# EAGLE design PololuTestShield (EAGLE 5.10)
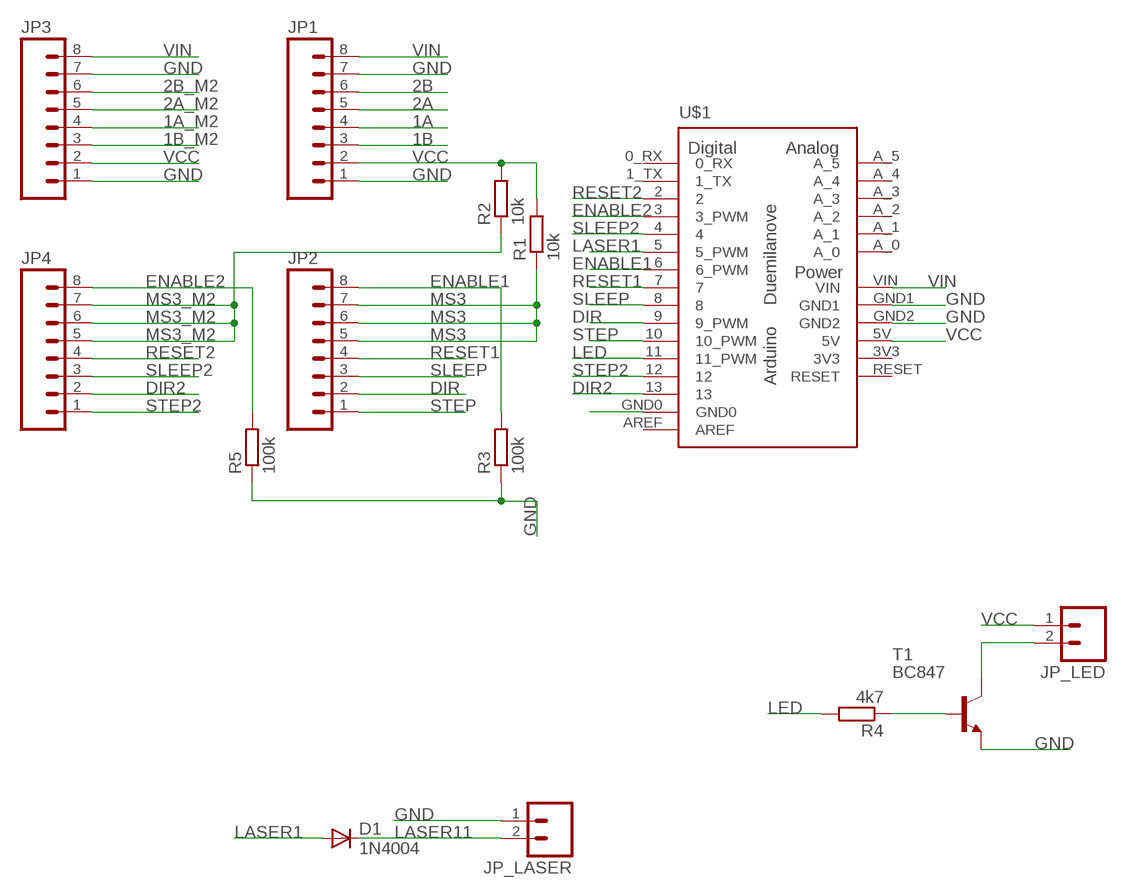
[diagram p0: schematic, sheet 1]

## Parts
D1  1N4004  [DO41-10]
JP1  M08LOCK_LONGPADS  [1X08_LOCK_LONGPADS]
JP2  M08LOCK_LONGPADS  [1X08_LOCK_LONGPADS]
JP3  M08LOCK_LONGPADS  [1X08_LOCK_LONGPADS]
JP4  M08LOCK_LONGPADS  [1X08_LOCK_LONGPADS]
JP_LASER  M02LOCK_LONGPADS  [1X02_LOCK_LONGPADS]
JP_LED  M02LOCK_LONGPADS  [1X02_LOCK_LONGPADS]
R1  10k  R-EU_M1206  [M1206]
R2  10k  R-EU_M1206  [M1206]
R3  100k  R-EU_M1206  [M1206]
R4  4k7  R-EU_M1206  [M1206]
R5  100k  R-EU_M1206  [M1206]
T1  BC847  [SOT23]
U$1  ARDUINO-USBLONG_PADS_TEXT  [SHIELD]

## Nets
1A: JP1.4
1A_M2: JP3.4
1B: JP1.3
1B_M2: JP3.3
2A: JP1.5
2A_M2: JP3.5
2B: JP1.6
2B_M2: JP3.6
DIR: JP2.2 U$1.9(9_PWM)
DIR2: JP4.2 U$1.13
ENABLE1: JP2.8 R3.2 U$1.6(6_PWM)
ENABLE2: JP4.8 R5.2 U$1.3(3_PWM)
GND: JP1.1 JP1.7 JP3.1 JP3.7 JP_LASER.1 R3.1 R5.1 T1.2(E) U$1.GND0 U$1.GND1 U$1.GND2
LASER1: D1.A U$1.5(5_PWM)
LASER11: D1.C JP_LASER.2
LED: R4.2 U$1.11(11_PWM)
MS3: JP2.5 JP2.6 JP2.7 R1.1
MS3_M2: JP4.5 JP4.6 JP4.7 R2.1
N$1: R4.1 T1.1(B)
N$2: JP_LED.2 T1.3(C)
RESET1: JP2.4 U$1.7
RESET2: JP4.4 U$1.2
SLEEP: JP2.3 U$1.8
SLEEP2: JP4.3 U$1.4
STEP: JP2.1 U$1.10(10_PWM)
STEP2: JP4.1 U$1.12
VCC: JP1.2 JP3.2 JP_LED.1 R1.2 R2.2 U$1.5V
VIN: JP1.8 JP3.8 U$1.VIN
Unconnected: U$1.0_RX U$1.1_TX U$1.A_0 U$1.A_1 U$1.A_2 U$1.A_3 U$1.A_4 U$1.A_5 U$1.AREF U$1.RESET

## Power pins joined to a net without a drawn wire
3V3: U$1.3V3

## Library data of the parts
D1 = diode:1N4004: DIODE
JP1-JP4 = SparkFun:M08: Header 8 Standard 8-pin 0.1" header. Use with straight break away headers (SKU : PRT-00116), right angle break away headers (PRT-00553), swiss pins (PRT-00743), machine pins (PRT-00117), and female headers (PRT-00115).
JP_LASER JP_LED = SparkFun:M02: Header 2
R1-R5 = rcl:R-EU_: RESISTOR, European symbol
T1 = transistor-neu-to92:BC847: NPN TRANSISTOR
U$1 = Arduino-Various:ARDUINO-USB: The Ardiuno Duemilanove Pinouts layoutet as a Bare Shield. v0.5 Also for Arduino Diecimila. This is designed as a Part and has no Outline in the Dimension Layer. The Outline, when present, is drawed at the tPlace / bPlace Layer. Library by Stephanie Lange, http://www.k-ita.de/~sl/

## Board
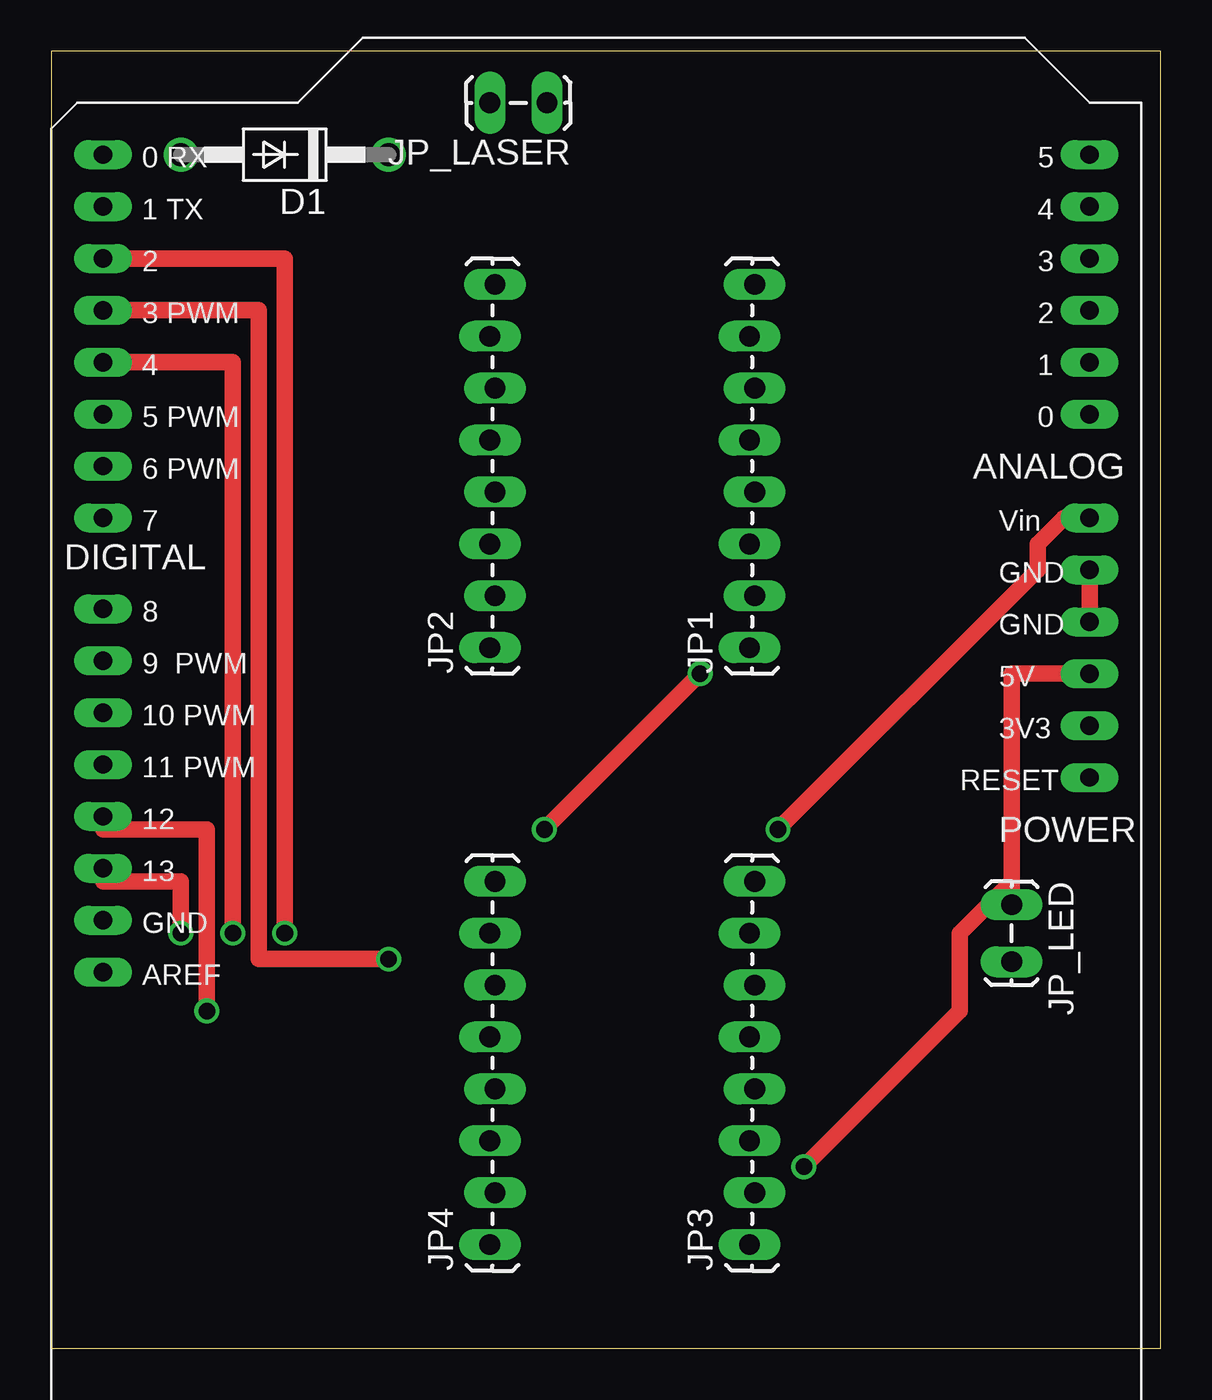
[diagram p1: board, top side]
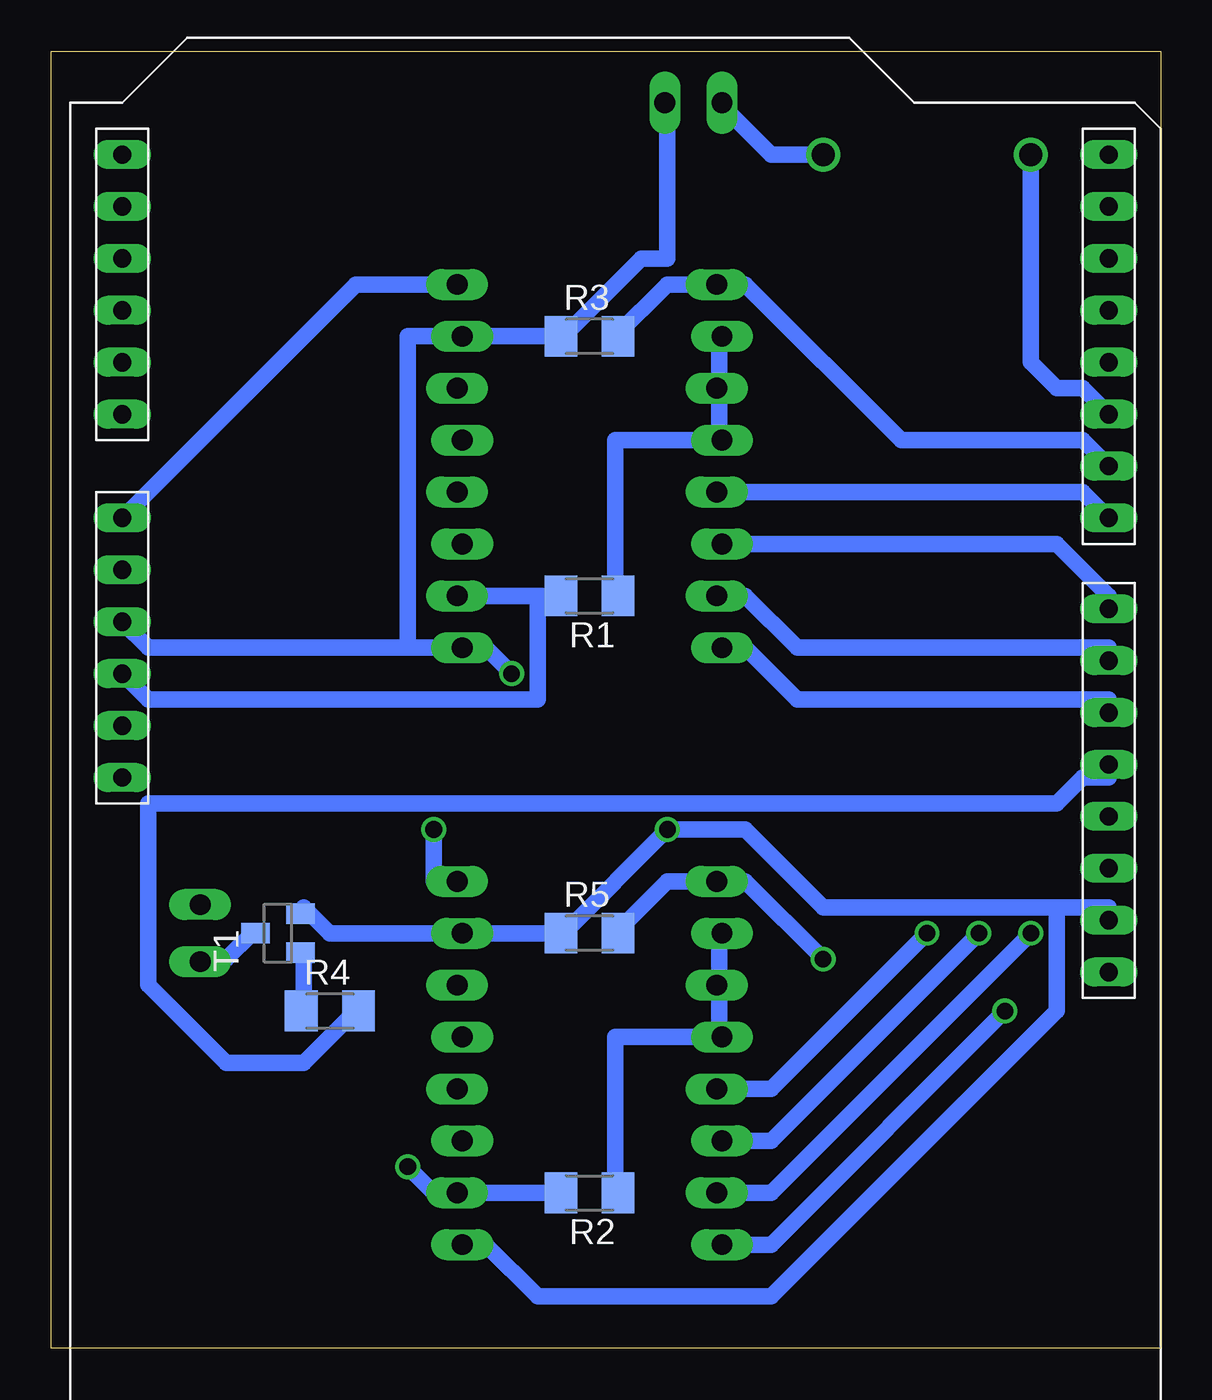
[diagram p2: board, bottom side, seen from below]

Size 54.28 x 63.49 mm. Coordinates in mm from the lower left corner, seen from the top.
Outline: 0,0 54.28,0 54.28,63.49 0,63.49 0,0
Copper layers (1*16): Top 0.035mm / dielectric 1.5mm / Bottom 0.035mm
Design rules "default *": minimum track width 32mil, minimum drill 32mil, track to track 8mil, track to pad 8mil, pad to pad 8mil, via to via 8mil, smd to smd 8mil, copper to edge 40mil, drill to drill 8mil, minimum pad ring 10mil, minimum via ring 8mil, stop-mask expansion 4mil, vias tented up to drill 0mil, thermal gap 10mil
tRestrict: area 20.3,33 to 22.9,53.3; area 33,33 to 35.6,53.3; area 20.3,3.8 to 22.9,24.1; area 33,3.8 to 35.6,24.1; area 20.3,59.7 to 25.4,62.2

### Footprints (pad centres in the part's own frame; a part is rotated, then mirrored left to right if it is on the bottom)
DO41-10 = drill 1.118 round: A 5.08,0; C -5.08,0
1X08_LOCK_LONGPADS = drill 1.016 long: 1 0,0.127; 2 2.54,-0.127; 3 5.08,0.127; 4 7.62,-0.127; 5 10.16,0.127; 6 12.7,-0.127; 7 15.24,0.127; 8 17.78,-0.127
1X02_LOCK_LONGPADS = drill 1.016 long: 1 -0.127,0; 2 2.667,0
M1206 = smd 1.6 x 2: 1 -1.4,0; 2 1.4,0
SOT23 = smd 1 x 1.4: 1 -0.95,-1.1; 2 0.95,-1.1; 3 0,1.1
SHIELD = drill 0.9 pad 1.27 long: 0_RX -25.4,27.94; 1_TX -25.4,25.4; 2 -25.4,22.86; 3 -25.4,20.32; 3V3 22.86,0; 4 -25.4,17.78; 5 -25.4,15.24; 5V 22.86,2.54; 6 -25.4,12.7; 7 -25.4,10.16; 8 -25.4,5.715; 9 -25.4,3.175; 10 -25.4,0.635; 11 -25.4,-1.905; 12 -25.4,-4.445; 13 -25.4,-6.985; A_0 22.86,15.24; A_1 22.86,17.78; A_2 22.86,20.32; A_3 22.86,22.86; A_4 22.86,25.4; A_5 22.86,27.94; AREF -25.4,-12.065; GND0 -25.4,-9.525; GND1 22.86,7.62; GND2 22.86,5.08; RESET 22.86,-2.54; VIN 22.86,10.16

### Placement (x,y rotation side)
D1  11.43,58.42 180 top
JP1  34.29,34.29 90 top
JP2  21.59,34.29 90 top
JP3  34.29,5.08 90 top
JP4  21.59,5.08 90 top
JP_LASER  24.13,60.96 180 top
JP_LED  46.99,21.59 270 top
R1  27.94,36.83 180 bottom
R2  27.94,7.62 180 bottom
R3  27.94,49.53 0 bottom
R4  40.64,16.51 0 bottom
R5  27.94,20.32 0 bottom
T1  43.18,20.32 90 bottom
U$1  27.94,30.48 0 top

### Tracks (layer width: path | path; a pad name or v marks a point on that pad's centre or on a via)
DIR
  Bottom 0.813: U$1.9 2.54,34.29 17.78,34.29 20.32,36.83 JP2.2
DIR2  (via drill 0.81)
  Top 0.813: v6.35,20.32 6.35,22.86 2.54,22.86 U$1.13
  Bottom 0.813: v6.35,20.32 19.05,7.62 JP4.2
ENABLE1
  Bottom 0.813: R3.2 26.67,49.53 24.13,52.07 JP2.8 20.32,52.07 12.7,44.45 3.81,44.45 U$1.6
ENABLE2  (via drill 0.81)
  Top 0.813: U$1.3 10.16,50.8 10.16,19.05 v16.51,19.05
  Bottom 0.813: R5.2 26.67,20.32 24.13,22.86 JP4.8 20.32,22.86 v16.51,19.05
GND  (via drill 0.81)
  Top 0.813: U$1.GND2 U$1.GND1 | v24.13,25.4 v31.75,33.02
  Bottom 0.813: 36.83,34.29 49.53,34.29 U$1.GND2 | 36.83,34.29 JP1.1 33.02,34.29 v31.75,33.02 | JP_LASER.1 24.13,60.96 24.13,53.34 25.4,53.34 29.21,49.53 R3.1 JP1.7 36.83,49.53 36.83,34.29 | T1.2 41.91,21.59 40.64,20.32 JP3.7 R5.1 29.21,20.32 v24.13,25.4 20.32,25.4 16.51,21.59 5.08,21.59 | 5.08,21.59 2.54,21.59 U$1.GND0 | 5.08,21.59 5.08,16.51 19.05,2.54 30.48,2.54 33.02,5.08 JP3.1
LASER1
  Bottom 0.813: U$1.5 3.81,46.99 5.08,46.99 6.35,48.26 D1.A
LASER11
  Bottom 0.813: D1.C 19.05,58.42 21.59,60.96 JP_LASER.2
LED
  Bottom 0.813: R4.2 39.37,16.51 41.91,13.97 45.72,13.97 49.53,17.78 49.53,26.67 5.08,26.67 3.81,27.94 2.54,27.94 U$1.11
MS3
  Bottom 0.813: 21.59,46.99 21.59,49.53 JP2.7 | 21.59,44.45 26.67,44.45 26.67,36.83 R1.1 | 21.59,44.45 21.59,46.99 | 21.59,46.99 JP2.6 | 21.59,44.45 JP2.5
MS3_M2
  Bottom 0.813: 21.59,17.78 21.59,20.32 JP4.7 | 21.59,15.24 26.67,15.24 26.67,7.62 R2.1 | 21.59,15.24 21.59,17.78 | 21.59,17.78 JP4.6 | 21.59,15.24 JP4.5
N$1
  Bottom 0.813: T1.1 41.91,19.05 41.91,16.51 R4.1
N$2
  Bottom 0.813: T1.3 44.45,20.32 45.72,19.05 46.99,19.05 JP_LED.2
RESET1
  Bottom 0.813: U$1.7 3.81,41.91 JP2.4
RESET2  (via drill 0.81)
  Top 0.813: U$1.2 11.43,53.34 v11.43,20.32
  Bottom 0.813: v11.43,20.32 19.05,12.7 JP4.4
SLEEP
  Bottom 0.813: U$1.8 2.54,36.83 5.08,39.37 JP2.3
SLEEP2  (via drill 0.81)
  Top 0.813: U$1.4 8.89,48.26 v8.89,20.32
  Bottom 0.813: v8.89,20.32 19.05,10.16 JP4.3
STEP
  Bottom 0.813: U$1.10 2.54,31.75 17.78,31.75 20.32,34.29 JP2.1
STEP2  (via drill 0.81)
  Top 0.813: v7.62,16.51 7.62,25.4 2.54,25.4 U$1.12
  Bottom 0.813: v7.62,16.51 19.05,5.08 JP4.1
VCC  (via drill 0.81)
  Top 0.813: U$1.5V 46.99,33.02 46.99,22.86 | 46.99,22.86 JP_LED.1 46.99,21.59 | v36.83,8.89 44.45,16.51 44.45,20.32 46.99,22.86
  Bottom 0.813: 30.48,36.83 R1.2 29.21,36.83 | 30.48,36.83 JP1.2 | 29.21,7.62 R2.2 JP3.2 35.56,7.62 v36.83,8.89 | 30.48,36.83 30.48,31.75 49.53,31.75 U$1.5V
VIN  (via drill 0.81)
  Top 0.813: v35.56,25.4 48.26,38.1 48.26,39.37 49.53,40.64 U$1.VIN
  Bottom 0.813: U$1.VIN 39.37,52.07 JP1.8 | v35.56,25.4 35.56,22.86 JP3.8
